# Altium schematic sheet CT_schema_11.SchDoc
size 390 x 385 mm
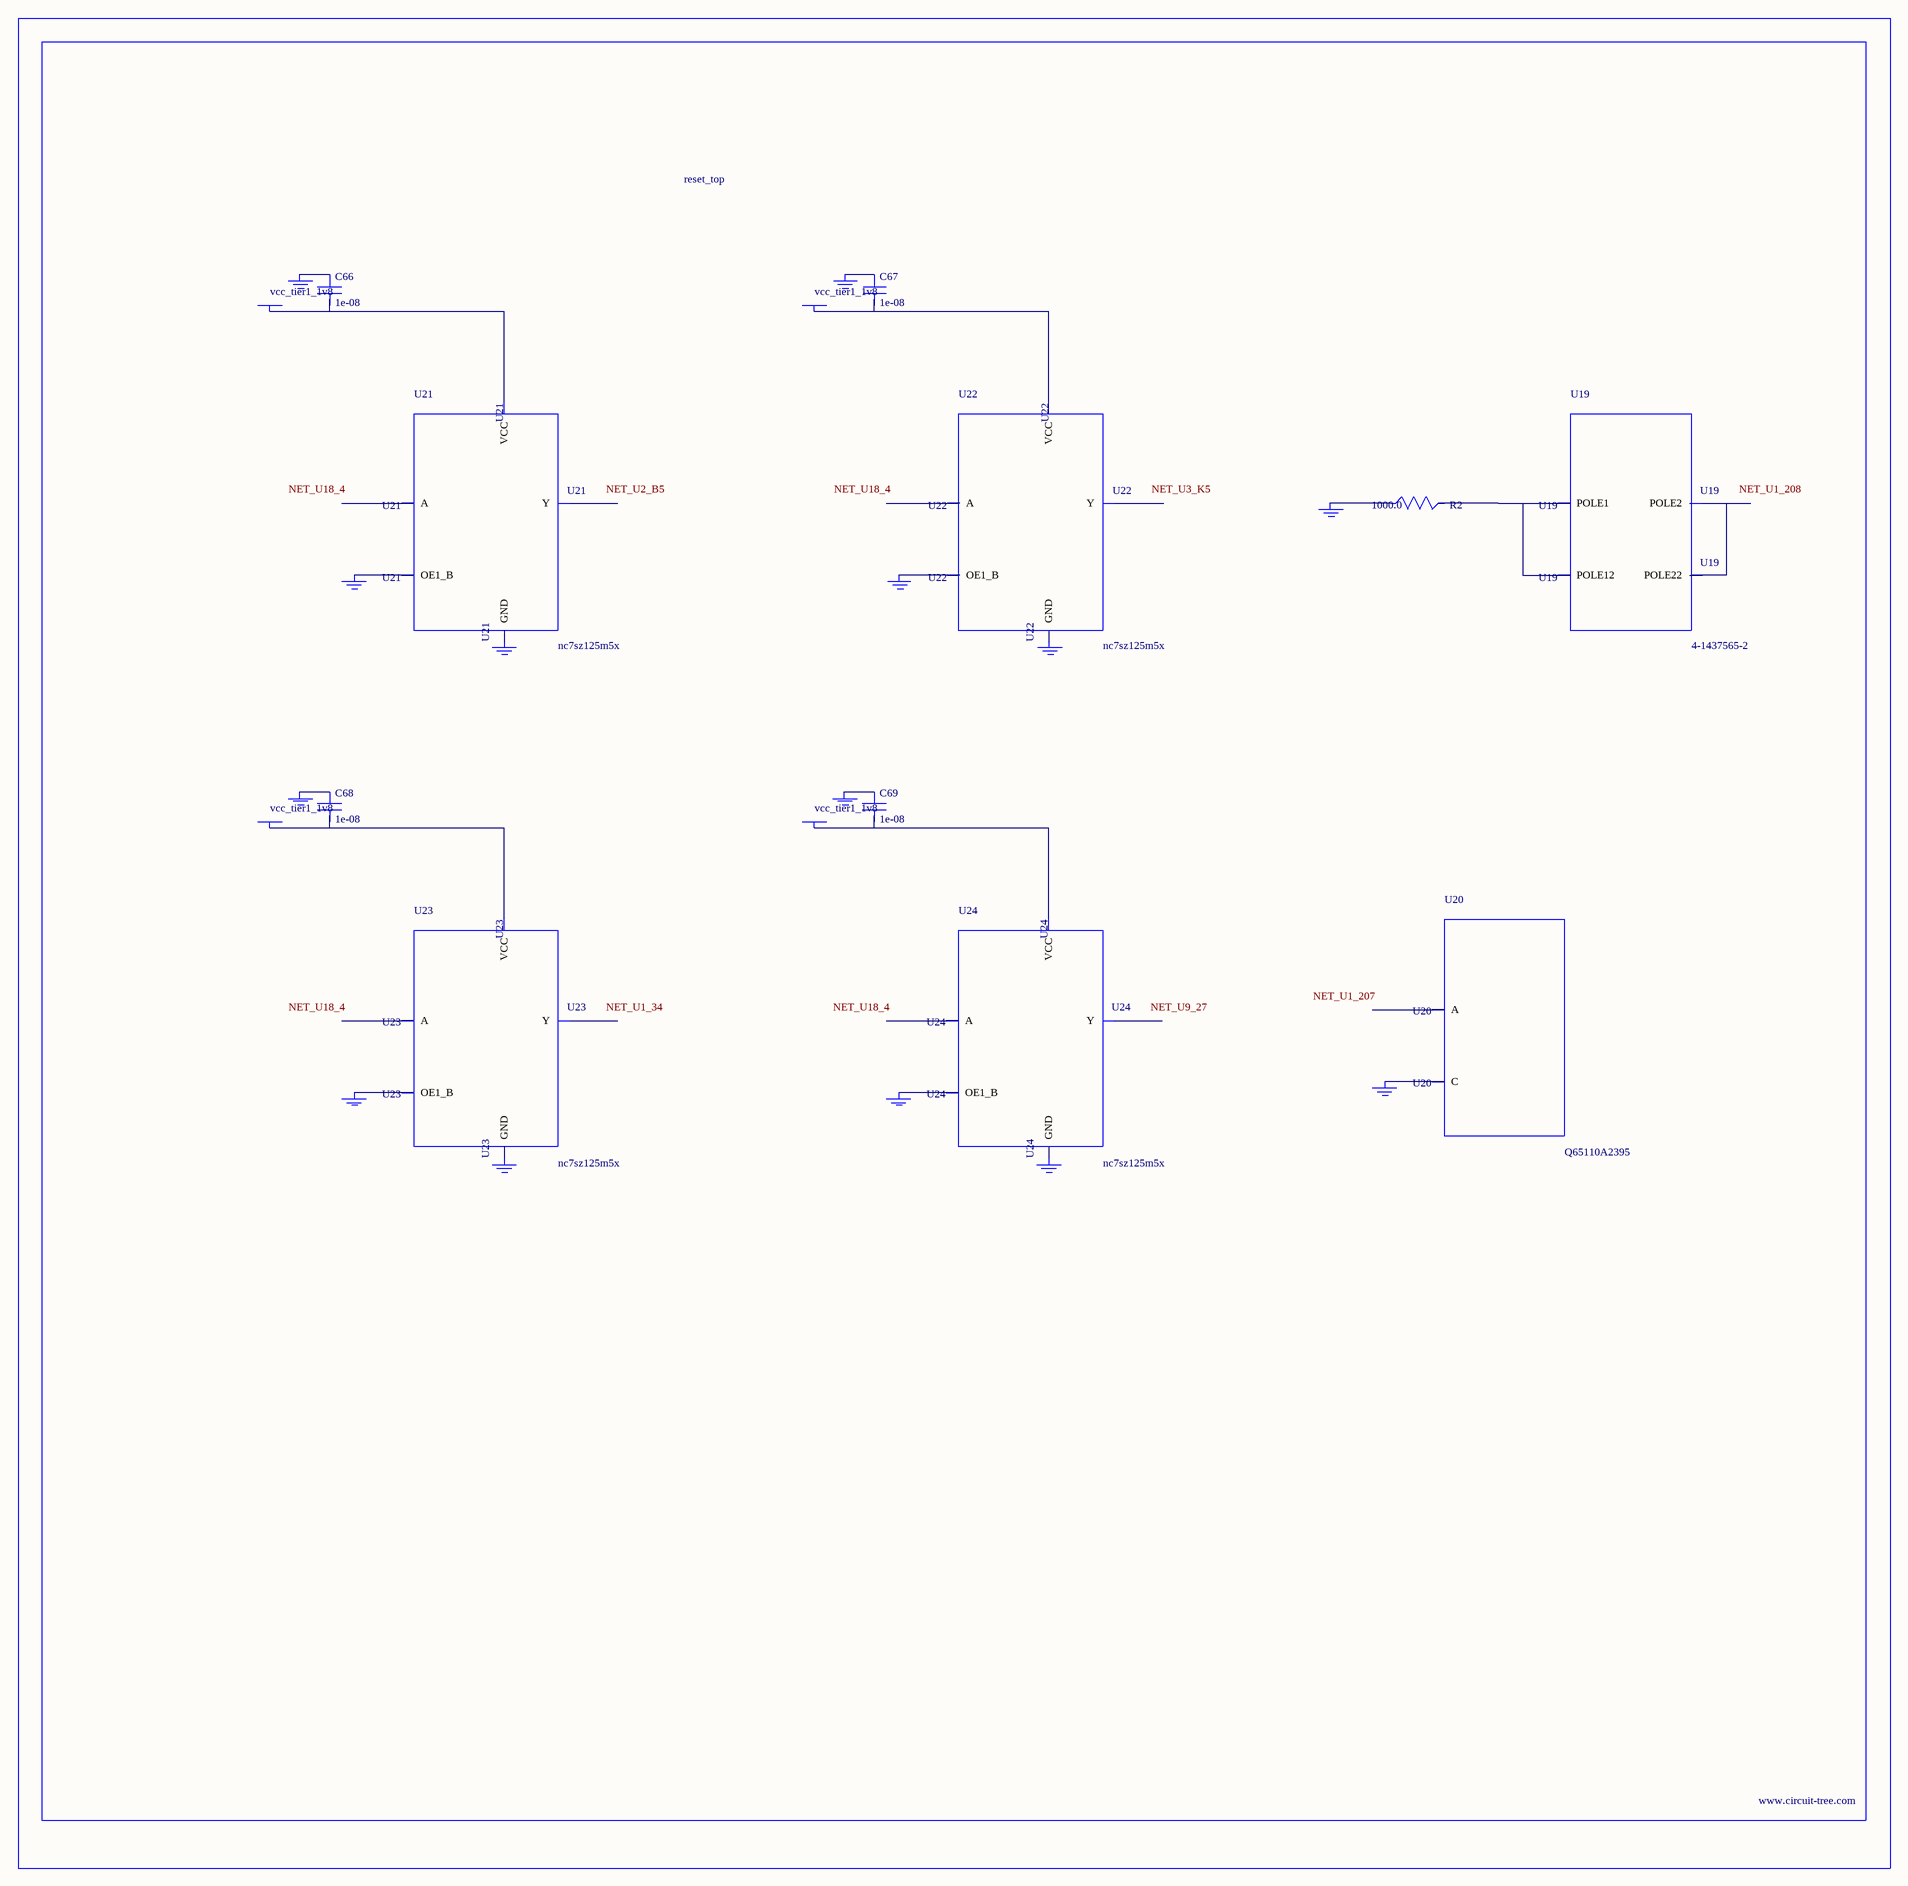
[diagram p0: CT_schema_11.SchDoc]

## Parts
BORDER10  (no value)
C66  1e-08  [C0402]
C67  1e-08  [C0402]
C68  1e-08  [C0402]
C69  1e-08  [C0402]
GND_INSTANCE_10_0  (no value)
GND_INSTANCE_10_1  (no value)
GND_INSTANCE_10_2  (no value)
GND_INSTANCE_10_3  (no value)
GND_INSTANCE_10_4  (no value)
GND_INSTANCE_10_5  (no value)
GND_INSTANCE_10_6  (no value)
GND_INSTANCE_10_7  (no value)
GND_INSTANCE_10_8  (no value)
GND_INSTANCE_10_9  (no value)
GND_INSTANCE_10_10  (no value)
GND_INSTANCE_10_11  (no value)
GND_INSTANCE_10_12  (no value)
GND_INSTANCE_10_13  (no value)
POWER_INSTANCE_10_0  vcc_tier1_1v8
POWER_INSTANCE_10_1  vcc_tier1_1v8
POWER_INSTANCE_10_2  vcc_tier1_1v8
POWER_INSTANCE_10_3  vcc_tier1_1v8
R2  1000.0  [R0603]
U19  4-1437565-2  [SW_4-1437565-2]
U20  Q65110A2395  [LGM67K-G1J2-24-Z]
U21  nc7sz125m5x  [NC7SZ125M5X]
U22  nc7sz125m5x  [NC7SZ125M5X]
U23  nc7sz125m5x  [NC7SZ125M5X]
U24  nc7sz125m5x  [NC7SZ125M5X]

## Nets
NetC66_1: C66.1 GND_INSTANCE_10_2.0(GND)
NetC66_2: C66.2 POWER_INSTANCE_10_0.0(PWR) U21.5(VCC)
NetC67_1: C67.1 GND_INSTANCE_10_5.0(GND)
NetC67_2: C67.2 POWER_INSTANCE_10_1.0(PWR) U22.5(VCC)
NetC68_1: C68.1 GND_INSTANCE_10_8.0(GND)
NetC68_2: C68.2 POWER_INSTANCE_10_2.0(PWR) U23.5(VCC)
NetC69_1: C69.1 GND_INSTANCE_10_11.0(GND)
NetC69_2: C69.2 POWER_INSTANCE_10_3.0(PWR) U24.5(VCC)
NetGND_INSTANCE_10_0_0: GND_INSTANCE_10_0.0(GND) R2.1
NetGND_INSTANCE_10_1_0: GND_INSTANCE_10_1.0(GND) U20.C
NetGND_INSTANCE_10_3_0: GND_INSTANCE_10_3.0(GND) U21.1(OE1_B)
NetGND_INSTANCE_10_4_0: GND_INSTANCE_10_4.0(GND) U21.3(GND)
NetGND_INSTANCE_10_6_0: GND_INSTANCE_10_6.0(GND) U22.1(OE1_B)
NetGND_INSTANCE_10_7_0: GND_INSTANCE_10_7.0(GND) U22.3(GND)
NetGND_INSTANCE_10_9_0: GND_INSTANCE_10_9.0(GND) U23.1(OE1_B)
NetGND_INSTANCE_10_10_0: GND_INSTANCE_10_10.0(GND) U23.3(GND)
NetGND_INSTANCE_10_12_0: GND_INSTANCE_10_12.0(GND) U24.1(OE1_B)
NetGND_INSTANCE_10_13_0: GND_INSTANCE_10_13.0(GND) U24.3(GND)
NetR2_2: R2.2 U19.1(POLE1) U19.2(POLE12)
NetU19_3: U19.3(POLE2) U19.4(POLE22)

Not connected (* = marked no-connect by the designer): U20 A; U21 2(A) 4(Y); U22 2(A) 4(Y); U23 2(A) 4(Y); U24 2(A) 4(Y)

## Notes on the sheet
- Labels drawn without touching a wire or pin: NET_U1_34, NET_U1_207, NET_U1_208, NET_U2_B5, NET_U3_K5, NET_U9_27, NET_U18_4

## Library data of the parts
BORDER10 = BORDER_PAGE10
C66-C69 = C0402C103K3RAC
GND_INSTANCE_10_0-GND_INSTANCE_10_13 = GND
POWER_INSTANCE_10_0-POWER_INSTANCE_10_3 = PWR
R2 = RC0603JR-071KL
